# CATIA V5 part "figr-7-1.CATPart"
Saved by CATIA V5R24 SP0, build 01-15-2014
Part number: Part1
Bounding box of the stored display mesh (mm): x -50 to 50, y -75 to 75, z 0 to 10
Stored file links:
  D:\KAVITA\CATIA V5-6R2014 Project_ Kavita\CATIA V5-6R2014_partfiles\Partfiles\c07_catia_v5-6r2014_prt\figr-7-1.CATPart
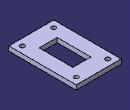
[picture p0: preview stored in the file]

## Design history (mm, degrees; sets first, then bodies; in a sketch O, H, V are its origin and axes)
Body1 (main body)
  Sketch1 on xy-plane, origin (0, 0, 0), H (1, 0, 0), V (0, 1, 0)
    line L1 (-50, 75) -> (50, 75)
    line L2 (50, 75) -> (50, -75)
    line L3 (50, -75) -> (-50, -75)
    line L4 (-50, -75) -> (-50, 75)
    axis line L5 (50, -75) -> (-50, 75)
    length L3 = 100
    length L2 = 150
    horizontal: L1 H, L3 H
    vertical: L2 V, L4 V
    midpoint: O L5
  Pad1: profile Sketch1, direction (0, 0, 1), length 10
  Sketch2 on face of Pad1, origin (0, 0, 10), H (1, 0, 0), V (0, 1, 0)
    line L1 (-20, 37.5) -> (20, 37.5)
    line L2 (20, 37.5) -> (20, -37.5)
    line L3 (20, -37.5) -> (-20, -37.5)
    line L4 (-20, -37.5) -> (-20, 37.5)
    axis line L5 (20, -37.5) -> (-20, 37.5)
    length L3 = 40
    length L2 = 75
    horizontal: L1 H, L3 H
    vertical: L2 V, L4 V
    midpoint: O L5
  Pocket1: profile Sketch2, direction (0, 0, -1), through (limit type 3)
  Sketch3 on face of Pad1, origin (-33.8832, 14.5619, 10), H (1, 0, 0), V (0, 1, 0)
    point P1 (68.8832, -74.5619)
    reference projected line E1 (-16.1168, -89.5619) -> (83.8832, -89.5619) from edge [face of Pad1 | face of Pad1]
    reference projected line E2 (83.8832, -89.5619) -> (83.8832, 60.4381) from edge [face of Pad1 | face of Pad1]
    distance P1 E1 = 15
    distance P1 E2 = 15
  Hole1: placed by Sketch3, at (35, -60, 10) direction (0, 0, -1), diameter 10, through (limit type 3)
  RectPattern1: of Hole1, direction 1 instances 2, spacing 70, along edge [face of Pad1 | face of Pad1] reversed, direction 2 instances 2, spacing 120, along edge [face of Pad1 | face of Pad1]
